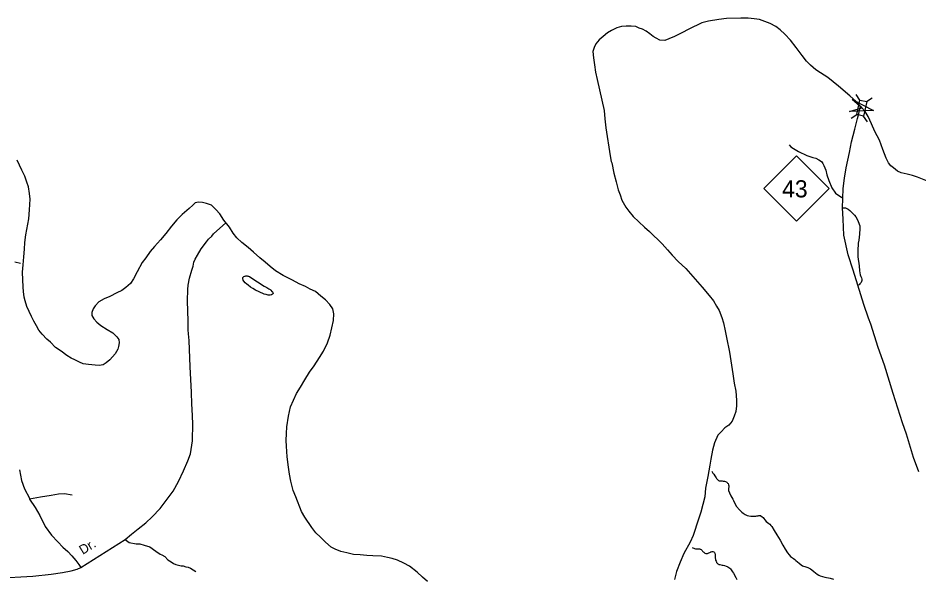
# Model space of a CAD drawing. Extents: x 2220236 to 2384410, y 720751 to 894131.
# Drawn here: x 2296936 to 2306111, y 885584 to 891304 of the extents above; entities that cross this region are included whole.
import ezdxf

# ---------------------------------------------------------------- set-up
doc = ezdxf.new("R2010")
doc.units = 0
doc.layers.add('Default', color=7, linetype='Continuous')

msp = doc.modelspace()

# ---------------------------------------------------------------- linework, layer by layer
at = {"layer": 'Default'}
for p, q in [((2305519.7, 890466.6), (2305482, 890524.4)), ((2305587.2, 890452.3), (2305645, 890489.9)), ((2305430.2, 890281.2), (2305488.1, 890318.8)), ((2305594.8, 890246.4), (2305557.1, 890304.2))]:
    msp.add_line(p, q, dxfattribs=at)
for points in [[(2305834.2, 889796.9), (2305809.9, 889828.5), (2305787.3, 889876.2), (2305754.3, 889963.9), (2305717.5, 890057.4), (2305672.4, 890145), (2305635.6, 890224.5), (2305602.7, 890298.2), (2305572.2, 890349.8), (2305533.9, 890391.4), (2305479.2, 890450.8), (2305416.6, 890510.1), (2305301.7, 890608.8), (2305190.7, 890695.5), (2305116.2, 890744.6), (2305069.8, 890774.2), (2305015.4, 890821.5), (2304973, 890865.2), (2304930.3, 890920.7), (2304867.5, 891004), (2304810.8, 891079.3), (2304752.1, 891138.7), (2304705.7, 891182.2), (2304661.3, 891215.6), (2304603, 891247), (2304496.5, 891287.9), (2304442.6, 891295.3), (2304378.4, 891302.6), (2304304.6, 891303.8), (2304158.5, 891298.2), (2304080.7, 891287.4), (2303976.9, 891272.4), (2303909.1, 891253.6), (2303775.8, 891190.1), (2303704.4, 891151.3), (2303628.8, 891116.6), (2303571, 891092.1), (2303531.3, 891073.6), (2303479.3, 891079.1), (2303443.1, 891096.6), (2303410.8, 891114.3), (2303376.6, 891143.9), (2303340.3, 891169.4), (2303304, 891191.2), (2303270, 891200.8), (2303233.7, 891216.3), (2303187.7, 891221.8), (2303135.9, 891221.3), (2303087.8, 891216.7), (2303042, 891202.2), (2302986.3, 891175.7), (2302946.6, 891153.3), (2302901.1, 891116.8), (2302859.5, 891082.3), (2302825.8, 891040.1), (2302808.3, 891003.8), (2302796.8, 890961.7), (2302801.4, 890897.8), (2302812.2, 890826), (2302825, 890752.1), (2302841.8, 890678.4), (2302911.2, 890359.1), (2302920, 890275.2), (2302929.1, 890185.4), (2302974, 889900.1), (2302984.8, 889842.1), (2302991, 889828.1), (2303012, 889720.6), (2303034.9, 889634.9), (2303055.9, 889553.1), (2303076.3, 889499.3), (2303092.9, 889445.4), (2303131.7, 889373.9), (2303162.1, 889334.2), (2303206.7, 889280.8), (2303323.9, 889170.1), (2303374.3, 889126.6), (2303503.6, 889000), (2303558.2, 888940.6), (2303606.7, 888885.2), (2303665.5, 888821.8), (2303744.2, 888748.8), (2303912.2, 888560.6), (2303983.1, 888475.4), (2304025.6, 888419.8), (2304056.3, 888364.2), (2304082.7, 888320.5), (2304111.5, 888250.8), (2304128, 888195.1), (2304144.9, 888115.3), (2304157.7, 888047.4), (2304189.3, 887895.8), (2304223.6, 887674.2), (2304238.7, 887580.5), (2304255.5, 887498.6), (2304262.4, 887406.8), (2304259.2, 887348.7), (2304253.8, 887290.6), (2304238.4, 887242.6), (2304216.8, 887192.3)], [(2306120.3, 886675.5), (2306066, 886824.3), (2305993.6, 887059.4), (2305954.3, 887177.1), (2305859.2, 887475.9), (2305770.1, 887764.8), (2305704.2, 887944), (2305631.6, 888181.3), (2305607, 888244.9), (2305559.4, 888384.4), (2305497.4, 888579.6), (2305449.7, 888733.1), (2305400.9, 888889.6), (2305356.1, 889091.3), (2305347.1, 889252.7), (2305342.6, 889369.3), (2305344.9, 889463.5), (2305347.1, 889564.4), (2305362.1, 889671.2), (2305378.5, 889775.8), (2305414.3, 889931.3), (2305433.8, 890041.9), (2305466.6, 890171.9), (2305495, 890279.5), (2305506.9, 890328.8), (2305515.9, 890360.2), (2305525.3, 890400.8)], [(2304796.2, 890011.6), (2304816.5, 889989.8), (2304842.6, 889972.1), (2304892.8, 889942.5), (2304979.4, 889901.5), (2305039.6, 889882.1), (2305069.5, 889874.6), (2305101.8, 889858.9), (2305126, 889839.3), (2305140.2, 889819.2), (2305150.4, 889799.4), (2305170.9, 889753.7), (2305182.8, 889705.6), (2305203.7, 889647.3), (2305233.6, 889571.1), (2305271, 889517.3), (2305293.4, 889499.3), (2305331.7, 889477.5), (2305344.9, 889463.5)], [(2297953.4, 887926.9), (2297927.9, 887880.6), (2297900.1, 887850.3), (2297872.5, 887819.9), (2297834.8, 887789.5), (2297803, 887769.2), (2297763.1, 887760.8), (2297721.2, 887764.3), (2297655.1, 887769.6), (2297601, 887777.2), (2297562.9, 887794.6), (2297516.7, 887818.1), (2297476.5, 887835.7), (2297432.2, 887863.3), (2297375.8, 887906.6), (2297319.3, 887945.9), (2297266.8, 887997.4), (2297230.5, 888029.1), (2297182, 888080.5), (2297147.5, 888122.1), (2297123.1, 888165.7), (2297098.5, 888213.5), (2297072, 888259.3), (2297027, 888360.7), (2297008.4, 888420.5), (2296997.9, 888456.3), (2296993.3, 888514.4), (2296986.9, 888558.1), (2296983.1, 888714), (2296988.3, 888786.1), (2296993.6, 888868.1), (2297002.7, 888948.1), (2297006, 889014.3), (2297015.1, 889094.3), (2297045.3, 889256.6), (2297054.4, 889346.6), (2297055.7, 889402.7), (2297059.1, 889456.7), (2297054.5, 889514.5), (2297041.9, 889582.4), (2297027.3, 889630.2), (2297004.6, 889691.9), (2296975.9, 889751.6), (2296926.9, 889855)], [(2306207.6, 889638.9), (2306105.3, 889679.7), (2306055.2, 889697.3), (2306001, 889710.7), (2305938.9, 889725.9), (2305902.6, 889743.5), (2305862.4, 889777), (2305834.2, 889796.9)], [(2300555, 885821.4), (2300491, 885824.8), (2300423, 885830), (2300354.9, 885835.4), (2300286.9, 885850.6), (2300226.6, 885866), (2300168.5, 885887.4), (2300128.2, 885909), (2300071.8, 885958.3), (2300019.3, 886009.7), (2299972.8, 886055.2), (2299932.2, 886108.8), (2299859, 886213.8), (2299826.4, 886273.5), (2299768.9, 886420.8), (2299742.2, 886486.6), (2299719, 886582.3), (2299702.4, 886652), (2299693.6, 886723.9), (2299678.5, 886829.7), (2299673.3, 886937.5), (2299670.7, 886995.7), (2299673.9, 887067.6), (2299677.1, 887135.6), (2299692.1, 887243.6), (2299715, 887340), (2299775.5, 887474.6), (2299814.8, 887539), (2299860, 887613.5), (2299909.1, 887693.9), (2299956.4, 887756.3), (2300009.5, 887840.9), (2300050.7, 887905.4), (2300091.8, 887991.7), (2300119, 888070.1), (2300136.1, 888144.2), (2300151.2, 888220.3), (2300154.5, 888286.2), (2300144.1, 888340.2), (2300113.5, 888383.8), (2300069.1, 888431.4), (2300024.8, 888468.8), (2299968.3, 888514.3), (2299916, 888539.6), (2299865.7, 888567.1), (2299803.3, 888594.4), (2299733.1, 888629.7), (2299638.6, 888678.7), (2299562, 888725.7), (2299507.6, 888769.1), (2299455.2, 888814.6), (2299400.8, 888858), (2299338.2, 888915.2), (2299281.6, 888962.7), (2299219.1, 889014), (2299166.5, 889061.5), (2299128.1, 889110.9), (2299091.4, 889170.6), (2299034.7, 889241.9), (2298992, 889307.4), (2298951.5, 889353), (2298907.1, 889396.6), (2298858.9, 889414), (2298816.9, 889423.5), (2298774.8, 889427.2), (2298742.9, 889418.7), (2298717.2, 889396.4), (2298679.7, 889360), (2298610.3, 889299.4), (2298554.9, 889246.9), (2298501.6, 889180.3), (2298442.4, 889105.6), (2298389.2, 889043), (2298328, 888974.5), (2298284.5, 888922.1), (2298239.2, 888859.6), (2298201.6, 888811.2), (2298150.7, 888716.7), (2298113.4, 888644.3), (2298084, 888595.9), (2298036.4, 888555.5), (2297994.8, 888527), (2297945, 888500.6), (2297873.5, 888463.8), (2297813.9, 888439.2), (2297760.1, 888408.6), (2297722.7, 888370.2), (2297703, 888338), (2297689.3, 888301.8), (2297689.7, 888271.8), (2297708, 888236.1), (2297738.4, 888202.4), (2297778.8, 888168.8), (2297845.1, 888127.5), (2297901.6, 888092.2), (2297942, 888052.7), (2297962.2, 888024.9), (2297968.6, 887990.9), (2297961, 887954.8), (2297953.4, 887926.9)], [(2305342.6, 889369.3), (2305371, 889367.9), (2305385.1, 889362.1), (2305399, 889354.2), (2305415.3, 889342.5), (2305435.4, 889320.7), (2305463.6, 889295.1), (2305477.9, 889275), (2305494.2, 889247.3), (2305502.4, 889227.4), (2305516.8, 889183.6), (2305519.1, 889157.7), (2305515.8, 889101.5), (2305508.4, 889037.6), (2305502.8, 889007.6), (2305497.6, 888931.5), (2305498.3, 888869.5), (2305511.2, 888775.6), (2305513.8, 888725.7), (2305522.3, 888685.8), (2305528.4, 888667.9), (2305536.6, 888654), (2305538.7, 888642.1), (2305538.9, 888626.1), (2305531.1, 888605.9), (2305519.3, 888591.9), (2305511.2, 888583.7), (2305497.4, 888579.6)], [(2296720.4, 885591.1), (2297088.7, 885614), (2297275.4, 885631.8), (2297389.7, 885649.6), (2297478.6, 885667.3), (2297539.5, 885682.6), (2297575.1, 885700.4), (2298027.2, 885987.6), (2298092, 886040.9), (2298161.8, 886094.3), (2298238, 886157.9), (2298302.8, 886216.3), (2298384, 886302.7), (2298517.4, 886480.6), (2298570.7, 886579.7), (2298624.1, 886686.5), (2298667.2, 886788.1), (2298695.2, 886859.3), (2298715.5, 886991.5), (2298718, 887169.4), (2298711.5, 887317.1), (2298707, 887367.1), (2298703.6, 887489), (2298691, 887748.8), (2298679.9, 888015.7), (2298674.9, 888084.3), (2298672.3, 888125), (2298672.3, 888211.4), (2298662.2, 888419.8), (2298667.2, 888534.2), (2298669.8, 888579.9), (2298685, 888651.1), (2298707.9, 888732.4), (2298720.6, 888773.1), (2298729.5, 888812.9), (2298743, 888845), (2298764.6, 888885.1), (2298803.9, 888951.6), (2298857.2, 889022.2), (2298878.9, 889048.3), (2298910.4, 889080.6), (2298930.2, 889104.8), (2299055.7, 889215.5)], [(2296960.2, 888799.7), (2296904.2, 888813.8)], [(2299445.6, 888570.1), (2299471.4, 888554.8), (2299493.1, 888544), (2299500.7, 888539.5), (2299506.2, 888535.6), (2299513.5, 888529.3), (2299524.2, 888516.7), (2299529.1, 888510.3), (2299532.9, 888503.9), (2299537, 888498.2), (2299537.5, 888495.8), (2299536.9, 888494.2), (2299531, 888488.2), (2299521, 888482.2), (2299507, 888478.2), (2299498.2, 888477), (2299487, 888478.2), (2299467, 888483.1), (2299447.1, 888489.7), (2299392.9, 888512.1), (2299356.4, 888529.4), (2299329.2, 888544.7), (2299307, 888557.8), (2299283, 888578.2), (2299268.9, 888589.9), (2299252.9, 888604), (2299238.9, 888619.8), (2299233, 888631.8), (2299231, 888635.9), (2299228.8, 888639.8), (2299226.9, 888644), (2299226.9, 888648), (2299227.4, 888650.6), (2299228.9, 888657.3), (2299231.2, 888661.3), (2299235, 888665.7), (2299238.9, 888668.3), (2299246.9, 888671.8), (2299252.1, 888672.8), (2299259.4, 888674.9), (2299266.1, 888674.2), (2299272.9, 888673.7), (2299279.1, 888673.1), (2299285.8, 888671.8), (2299294.9, 888668.2), (2299330.9, 888644), (2299378.4, 888612.4), (2299445.6, 888570.1)], [(2304216.8, 887192.3), (2304181.2, 887152), (2304141.6, 887123.6), (2304106, 887083.3), (2304070.4, 887048.8), (2304035.4, 886972.5), (2304016, 886898.3), (2303999, 886804.2), (2303989.8, 886746), (2303969, 886629.9), (2303946.3, 886509.7), (2303937.3, 886421.7), (2303918.1, 886343.5), (2303896.9, 886265.2), (2303873.7, 886193), (2303819.6, 886028.5), (2303788.3, 885958.2), (2303725.5, 885843.6), (2303686.6, 885755.1), (2303649.5, 885658.8), (2303628.4, 885578.7)], [(2296950.3, 886696.7), (2296970.6, 886587.4), (2297003.6, 886503.5), (2297051.9, 886409.5), (2297054.4, 886396.8)], [(2304009, 886683.6), (2304020.2, 886663.7), (2304028.3, 886651.6), (2304040.4, 886635.7), (2304046.4, 886625.3), (2304052.4, 886615.8), (2304058.3, 886607.8), (2304070.1, 886594.3), (2304078.4, 886587.2), (2304084.3, 886584.3), (2304088.3, 886583.6), (2304096.3, 886584), (2304114.3, 886583.9), (2304126.4, 886581.8), (2304137.5, 886579.9), (2304148.6, 886577.1), (2304162.1, 886571.1), (2304165.2, 886567.8), (2304170.3, 886561.6), (2304174.5, 886556), (2304180.2, 886544.6), (2304182.4, 886533.3), (2304182.7, 886527.5), (2304180.4, 886503.6), (2304180.4, 886485.6), (2304188.4, 886461.3), (2304202.3, 886433.3), (2304222.3, 886399.5), (2304230.4, 886383.4), (2304258.5, 886327.1), (2304294.4, 886285.2), (2304314.5, 886265.4), (2304328.3, 886253.8), (2304348.3, 886240.6), (2304368.5, 886231.6), (2304386.5, 886226.5), (2304408.4, 886223.4), (2304419.6, 886223.1), (2304436.4, 886223.8), (2304448.8, 886224.3), (2304458.6, 886225.5), (2304468.5, 886227.5), (2304480.4, 886229.6), (2304490.1, 886230.8), (2304499.9, 886231.2), (2304506.4, 886229.8), (2304510.5, 886227.6), (2304523.7, 886218.1), (2304532.4, 886209.5), (2304540.5, 886199.2), (2304550.5, 886187.4), (2304562.4, 886171.5), (2304576.5, 886159.7), (2304590.4, 886151.3), (2304600.6, 886143.5), (2304612.3, 886129.9), (2304620.6, 886119.7), (2304646.4, 886079.7), (2304672.5, 886033.2), (2304704.5, 885979.5), (2304734.6, 885929.1), (2304756.4, 885889.8), (2304780.5, 885849.7), (2304796.5, 885829), (2304812.6, 885813.2), (2304842.6, 885793.3), (2304854.6, 885783.7), (2304866.6, 885773.6), (2304882.6, 885759.5), (2304898.5, 885743.7), (2304919.9, 885728.2), (2304934.5, 885719.8), (2304968.6, 885707.2), (2304986.7, 885701.3), (2305002.5, 885695.6), (2305015, 885688.7), (2305030.6, 885677.7), (2305050.6, 885659.7), (2305082.7, 885633.2), (2305098.7, 885623.9), (2305112.8, 885617.1), (2305137.9, 885608.3), (2305160.6, 885601), (2305214.7, 885591), (2305248.7, 885581.6)], [(2297488.7, 886440), (2297410, 886452.7), (2297349, 886447.6), (2297275.4, 886434.9), (2297163.6, 886419.6), (2297090, 886404.4), (2297054.4, 886396.8)], [(2297054.4, 886396.8), (2297110.3, 886312.9), (2297158.6, 886231.6), (2297214.4, 886119.7), (2297277.9, 886030.8), (2297341.4, 885962.2), (2297392.2, 885908.8), (2297443, 885863), (2297483.7, 885819.8), (2297524.3, 885774.1), (2297554.8, 885730.9), (2297575.1, 885700.4)], [(2298027.2, 885987.6), (2298067.8, 885954.5), (2298138.9, 885941.8), (2298177, 885941.8), (2298222.8, 885929.1), (2298278.6, 885911.3), (2298340.9, 885868.1), (2298386.6, 885837.6), (2298403, 885831.1), (2298432.3, 885812.2), (2298462.8, 885780.6), (2298496.5, 885759.4), (2298522.7, 885741.7), (2298544.7, 885732), (2298598.8, 885718.6), (2298620.9, 885716.7), (2298646.9, 885707), (2298669.1, 885703.3), (2298693, 885695.6), (2298747.4, 885662.1)], [(2303809.5, 885904.1), (2303833.1, 885893.7), (2303844.2, 885891.8), (2303856.2, 885891.4), (2303864.2, 885891.8), (2303869.8, 885892), (2303877, 885891.3), (2303884.4, 885890.8), (2303890.3, 885889.4), (2303894, 885888), (2303899.1, 885885), (2303904.3, 885881), (2303910.4, 885873.1), (2303915.4, 885866.7), (2303922.3, 885859.5), (2303926.3, 885856.5), (2303932.2, 885852.5), (2303939.2, 885848.8), (2303948.3, 885845), (2303954, 885843.6), (2303958.2, 885843.8), (2303962.2, 885844), (2303966.4, 885844.9), (2303972.2, 885847.8), (2303978.4, 885849.6), (2303987.8, 885853.2), (2303994.7, 885856.9), (2304000, 885859.5), (2304004.3, 885861.3), (2304012.4, 885863.2), (2304020.2, 885863.6), (2304028.7, 885860.7), (2304033.7, 885856.7), (2304036.2, 885853.6), (2304038.6, 885848.7), (2304040.2, 885844.8), (2304041.7, 885838.2), (2304042.3, 885831.7), (2304042.4, 885821.1), (2304043.4, 885810.5), (2304044.4, 885801.5), (2304045, 885795.8), (2304046.1, 885788.4), (2304048.4, 885777.1), (2304052.2, 885765.6), (2304056.4, 885757.6), (2304058.3, 885753.7), (2304060.3, 885749.6), (2304062.9, 885745.7), (2304066.4, 885741.6), (2304070.3, 885739.4), (2304075.7, 885736.2), (2304082.2, 885733.3), (2304090.9, 885731.2), (2304114.1, 885726.4), (2304126.4, 885723.7), (2304137.7, 885720.7), (2304156.4, 885714.9), (2304164.5, 885712), (2304172.3, 885707.3), (2304183, 885700.4), (2304191.4, 885694.3), (2304198.1, 885688), (2304207.2, 885676), (2304220.9, 885658.5), (2304230.3, 885643.3), (2304254.9, 885600.9), (2304264.4, 885579.1)], [(2301109.6, 885559.6), (2301061.2, 885603.1), (2301004.6, 885654.4), (2300926.1, 885715.6), (2300867.8, 885746.8), (2300805.4, 885774.3), (2300751.3, 885791.6), (2300701.2, 885803), (2300641, 885816.3), (2300555, 885821.4)]]:
    msp.add_lwpolyline(points, dxfattribs=at)
for points in [[(2305441.4, 890473.7), (2305656.9, 890359.7), (2305413.2, 890350.7), (2305538.1, 890386.9)], [(2305488.1, 890318.8), (2305519.3, 890466.6), (2305588.4, 890452), (2305557.1, 890304.2)], [(2304538.6, 889564.4), (2304871.6, 889897.4), (2305204.6, 889564.4), (2304871.6, 889231.4)]]:
    msp.add_lwpolyline(points, close=True, dxfattribs=at)

# ---------------------------------------------------------------- texts
msp.add_text('43', height=175, dxfattribs=at).set_placement((2304725.7, 889474.7))
msp.add_text('Dr.', height=95, rotation=31.25444, dxfattribs=at).set_placement((2297595.3, 885829.9))

doc.saveas('drawing.dxf')
